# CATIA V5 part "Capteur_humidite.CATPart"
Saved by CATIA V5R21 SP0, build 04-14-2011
Part number: Capteur_humidite
Bounding box of the stored display mesh (mm): x -12.62 to 14.6, y -8.35 to 8.35, z 0 to 7.2
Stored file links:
  C:\Users\zerma\Pictures\Stage Stomate\Capteur_humidite.CATPart
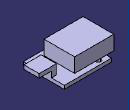
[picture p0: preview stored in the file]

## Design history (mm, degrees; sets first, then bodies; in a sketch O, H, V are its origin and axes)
Body1 (main body)
  Sketch1 on xy-plane, origin (0, 0, 0), H (1, 0, 0), V (0, 1, 0)
    line L1 (9.6, 8.35) -> (9.6, -8.35)
    line L2 (9.6, -8.35) -> (-9.6, -8.35)
    line L3 (-9.6, -8.35) -> (-9.6, 8.35)
    line L4 (-9.6, 8.35) -> (9.6, 8.35)
    length L1 = 16.7
    length L4 = 19.2
    vertical: L1 V, L3 V
    horizontal: L2 H, L4 H
    equidistance: L1 L3 O, L2 L4 O
  Pad1: profile Sketch1, direction (0, 0, 1), length 1.4
  Sketch2 on end face of Pad1, origin (0, 0, 1.4), H (1, 0, 0), V (0, 1, 0)
    point P1 (-4.66, 0)
    line L1 (3.3, 6.24) -> (3.3, -6.24)
    line L2 (3.3, -6.24) -> (-12.62, -6.24)
    line L3 (-12.62, -6.24) -> (-12.62, 6.24)
    line L4 (-12.62, 6.24) -> (3.3, 6.24)
    reference projected line E1 (9.6, -8.35) -> (9.6, 8.35) from edge [face of Pad1 from Sketch1.L1 | end face of Pad1]
    distance L1 E1 = 6.3
    length L4 = 15.92
    length L3 = 12.48
    vertical: L1 V, L3 V
    horizontal: L2 H, L4 H
    equidistance: L1 L3 P1, L2 L4 P1
    symmetry: L4 L2 H
  Pad2: profile Sketch2, direction (0, 0, 1), length 5.8
  Sketch3 on start face of Pad1, origin (0, 0, 0), H (1, 0, 0), V (0, -1, 0)
    circle A1 centre (-6.1, -6.45) radius 1
    point P1 (-6.1, -6.45)
    reference projected line E1 (9.6, -8.35) -> (-9.6, -8.35) from edge [start face of Pad1 | face of Pad1 from Sketch1.L4]
    reference projected line E2 (-9.6, -8.35) -> (-9.6, 8.35) from edge [start face of Pad1 | face of Pad1 from Sketch1.L3]
    circle A2 centre (-6.1, 6.45) radius 1
    radius A1 = 1
    distance P1 E1 = 1.9
    distance P1 E2 = 3.5
    symmetry: A1 A2 H
  Pocket1: profile Sketch3, direction (0, 0, 1), length 1.4
  Sketch4 on end face of Pad1, origin (0, 0, 1.4), H (1, 0, 0), V (0, 1, 0)
    point P1 (8.6, 0)
    line L1 (9.6, 3.1) -> (9.6, -3.1)
    line L2 (9.6, -3.1) -> (7.6, -3.1)
    line L3 (7.6, -3.1) -> (7.6, 3.1)
    line L4 (7.6, 3.1) -> (9.6, 3.1)
    reference projected line E1 (9.6, -8.35) -> (9.6, 8.35) from edge [face of Pad1 from Sketch1.L1 | end face of Pad1]
    length L4 = 2
    length L1 = 6.2
    vertical: L1 V, L3 V
    horizontal: L2 H, L4 H
    equidistance: L1 L3 P1, L2 L4 P1
    coincidence: L1 E1
    symmetry: L4 L2 H
  Pad3: profile Sketch4, direction (0, 0, 1), length 2.4
  Sketch5 on end face of Pad3, origin (0, 0, 3.8), H (1, 0, 0), V (0, 1, 0)
    circle A1 centre (8.6, -2.0665) radius 0.25
    point P1 (8.6, -2.0665)
    reference projected line E1 (7.6, -3.1) -> (9.6, -3.1) from edge [face of Pad3 from Sketch4.L2 | end face of Pad3]
    reference projected line E2 (7.6, 3.1) -> (7.6, -3.1) from edge [face of Pad3 from Sketch4.L3 | end face of Pad3]
    radius A1 = 0.25
    distance P1 E1 = 1.0335
    distance P1 E2 = 1
  Plane1: type Offset, RefPlane yz-plane, Offset 20
  Sketch6 on Plane1, origin (20, 0, 0), H (0, 1, 0), V (0, 0, 1)
    circle A1 centre (-2.065, 5.9) radius 0.25
    point P1 (-2.065, 5.9)
    point P2 (0, 5.9)
    point P3 (-2.065, 5.9)
    radius A1 = 0.25
    distance P1 H = 5.9
    coincidence: P3 P1
  Sketch7 on end face of Pad3, origin (0, 0, 3.8), H (1, 0, 0), V (0, 1, 0)
    point P1 (8.6, -2.0665)
    reference projected circle E1 centre (8.6, -2.0665) radius 0.25 from Sketch5.A1
    concentricity: P1 E1
  Plane2: type 2Lines, Element1 edge [face of Pad3 | face of Pad3 from Sketch4.L2], Element2 edge [face of Pad3 from Sketch4.L2 | end face of Pad3]
  Plane3: type OffsetPt, RefPlane Plane2, RefPoint Sketch7
  Sketch8 on Plane3, origin (0, -2.0665, 0), H (-1, 0, 0), V (0, 0, 1)
    line L1 (-20, 5.9) -> (-8.6, 5.9)
    point P1 (-20, 5.9)
    point P2 (-8.6, 5.9)
    reference projected point E1 (-20, 5.9) from Sketch6.P3
    line L2 (-8.6, 5.9) -> (-8.6, 3.8)
    point P3 (-8.6, 3.8)
    point P4 (-8.6, 5.9)
    reference projected point E2 (-8.6, 3.8) from Sketch7
    horizontal: L1 H
    coincidence: P1 E1, P3 E2, P2 P4
    vertical: L2 V
  Sketch9 on face of Pad3 from Sketch4.L2, origin (0, -3.1, 0), H (1, 0, 0), V (0, 0, 1)
    line L1 (7.6, 5.4) -> (14.6, 5.4)
    line L2 (14.6, 3.8) -> (7.6, 3.8)
    line L3 (7.6, 3.8) -> (7.6, 5.4)
    point P2 (14.6, 5.4)
    reference projected line E1 (7.6, 3.8) -> (9.6, 3.8) from edge [face of Pad3 from Sketch4.L2 | end face of Pad3]
    reference projected line E2 (7.6, 1.4) -> (7.6, 3.8) from edge [face of Pad3 from Sketch4.L2 | face of Pad3 from Sketch4.L3]
    line L4 (14.6, 3.8) -> (14.6, 5.4)
    point P5 (14.6, 5.4)
    distance L1 L2 = 1.6
    length L1 = 7
    horizontal: L1 H, L2 H
    vertical: L3 V, L4 V
    coincidence: L2 E1, L3 E2, P5 P2
  Pad4: profile Sketch9, direction (0, 1, 0), length 6.2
